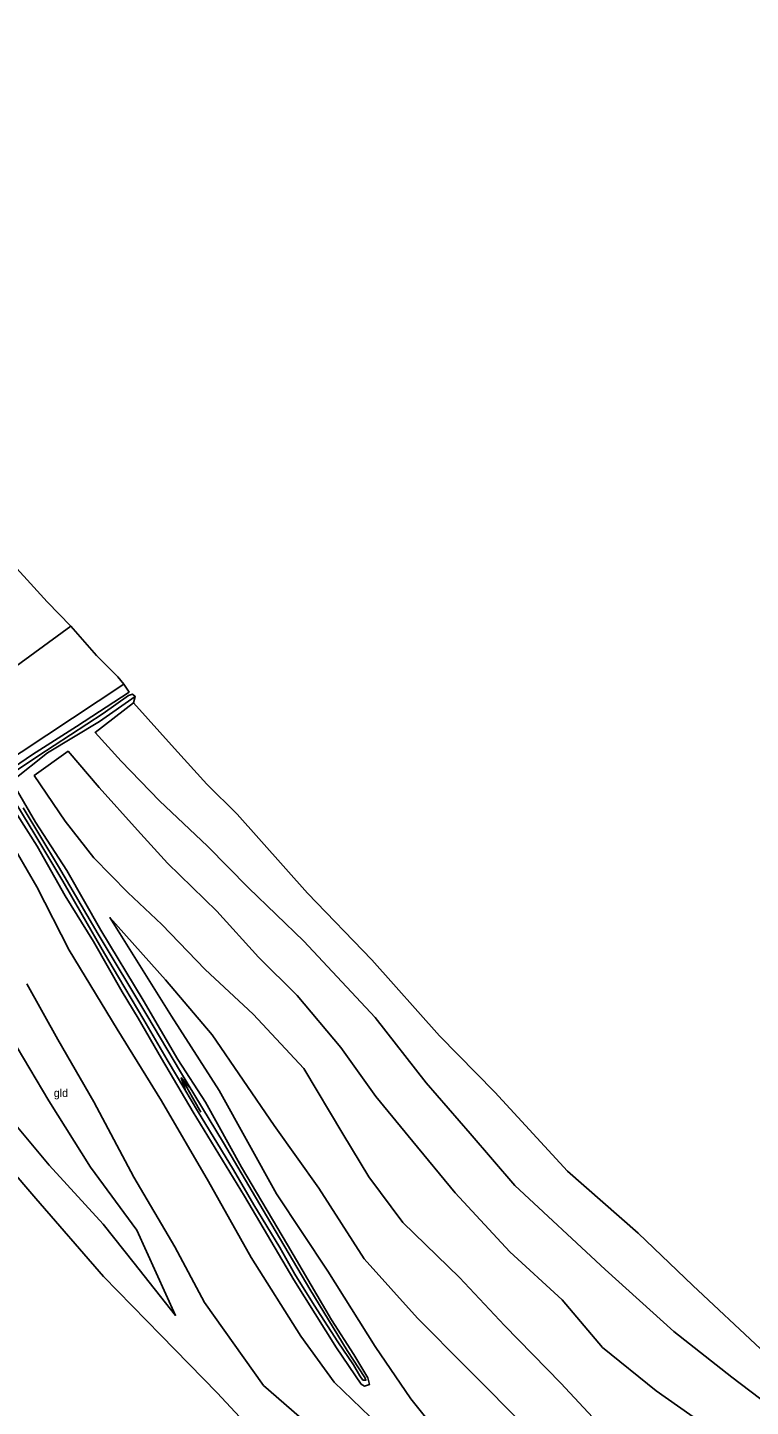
# Model space of a CAD drawing. Extents: x 154825 to 158680, y 370717 to 378075.
# Drawn here: x 155334.4 to 155424.8, y 377327.8 to 377500.1 of the extents above; entities that cross this region are included whole.
import ezdxf

# ---------------------------------------------------------------- set-up
doc = ezdxf.new("R2010")
doc.units = 0
for name, color, linetype in [('cultuurscheiding', 7, 'Continuous'), ('grasland_productiegrasl(vs)', 7, 'Continuous'), ('hoogteverschillijn', 7, 'Continuous'), ('insteek sloot', 7, 'Continuous'), ('Sloot bodem', 7, 'Continuous'), ('stroomrichting  watergangen', 7, 'Continuous'), ('vlak_akkerland', 7, 'Continuous'), ('vlak_Bos', 7, 'Continuous'), ('vlak_Grasland', 7, 'Continuous'), ('vlak_Grazige_vegetatie', 7, 'Continuous')]:
    doc.layers.add(name, color=color, linetype=linetype)

msp = doc.modelspace()

# ---------------------------------------------------------------- linework, layer by layer
at = {"layer": 'cultuurscheiding'}
msp.add_lwpolyline([(155308.09, 377402.13), (155339.81, 377425.31)], dxfattribs=at)
at = {"layer": 'hoogteverschillijn'}
for points in [[(155345.69, 377418.94), (155343.05, 377421.61), (155339.81, 377425.31), (155336.86, 377428.35), (155331.01, 377434.77), (155328.82, 377437.22), (155325.13, 377441.16), (155319.36, 377447.52), (155315.71, 377451.41), (155307.43, 377460.53), (155304.18, 377464.14), (155296.66, 377472.4), (155289.32, 377480.42), (155286.49, 377483.54), (155277.99, 377492.89), (155272.59, 377498.64), (155264.04, 377508.09)], [(155431.86, 377324.38), (155422.53, 377331.44), (155415.24, 377337.17), (155406.68, 377344.9), (155395.37, 377355.4), (155389.8, 377361.89), (155384.27, 377368.22), (155377.9, 377376.37), (155368.99, 377385.91), (155362.04, 377392.58), (155356.93, 377397.79), (155350.92, 377403.47), (155346.14, 377408.41), (155342.86, 377411.99), (155347.67, 377415.7), (155352.79, 377409.99), (155356.85, 377405.55), (155360.64, 377401.81), (155369.42, 377391.91), (155377.47, 377383.61), (155385.94, 377374.1), (155392.86, 377367.05), (155401.97, 377357.18), (155410.79, 377349.42), (155417.64, 377342.88), (155426.1, 377334.99)], [(155407.36, 377323.99), (155401.12, 377330.71), (155394.08, 377337.91), (155388.46, 377343.89), (155381.35, 377350.76), (155377.11, 377356.48), (155373.85, 377361.84), (155368.96, 377370.03), (155362.64, 377376.82), (155356.65, 377382.39), (155351.23, 377388.02), (155346.98, 377392.01), (155342.7, 377396.35), (155339.13, 377400.91), (155335.26, 377406.61), (155339.49, 377409.65), (155343.37, 377405.14), (155348.17, 377399.81), (155351.91, 377395.68), (155358.08, 377389.66), (155363.29, 377383.92), (155368.15, 377379.12), (155373.62, 377372.65), (155377.97, 377366.51), (155382.59, 377360.9), (155387.92, 377354.49), (155394.75, 377347.11), (155401.3, 377341.11), (155406.33, 377335.16), (155413.03, 377329.72), (155421.48, 377323.81)], [(155330.7, 377401.06), (155335.57, 377392.72), (155339.63, 377384.81), (155345.62, 377374.95), (155351.17, 377365.97), (155357.03, 377355.9), (155362.38, 377346.4), (155368.59, 377336.57), (155372.76, 377330.83), (155377.26, 377326.47)], [(155390.44, 377318.66), (155382.35, 377328.72), (155377.89, 377335.29), (155371.96, 377344.67), (155365.55, 377354.35), (155358.39, 377367.26), (155352.41, 377376.57), (155344.71, 377388.88), (155351.68, 377381.1), (155357.52, 377374.21), (155365.25, 377362.89), (155370.85, 377355.06), (155376.51, 377346.25), (155383.2, 377338.81), (155389.23, 377332.72), (155397.25, 377324.7)], [(155371.27, 377324.01), (155363.93, 377330.42), (155356.54, 377340.78), (155352.84, 377347.74), (155347.73, 377356.45), (155342.72, 377365.85), (155338.21, 377373.66), (155334.34, 377380.6)], [(155332.32, 377373.98), (155337.09, 377365.98), (155342.27, 377357.68), (155348.08, 377349.81), (155352.94, 377339.16), (155347.75, 377345.67), (155343.86, 377350.56), (155337.12, 377357.92), (155331.91, 377364.19)], [(155328.22, 377362.13), (155335.45, 377353.76), (155343.9, 377344.01), (155351.07, 377336.69), (155358.13, 377329.5), (155366.03, 377321.03)]]:
    msp.add_lwpolyline(points, dxfattribs=at)
at = {"layer": 'insteek sloot'}
for points in [[(155211.48, 377507.88), (155226.17, 377491.27), (155237.93, 377478.16), (155255.88, 377458.77), (155264.39, 377449.32), (155266.19, 377447.17), (155270.04, 377443.34), (155275.44, 377437.23), (155279.4, 377432.67), (155280.56, 377431.47), (155285.74, 377425.85), (155291.46, 377420.27), (155297.9, 377412.84), (155308.09, 377402.13), (155313.54, 377396.56), (155319.32, 377400.17), (155333.61, 377409.55), (155346.46, 377418.03)], [(155332.6, 377406.06), (155336.93, 377409.48), (155343.4, 377413.36), (155347.88, 377416.5)], [(155331.8, 377403.82), (155335.61, 377397.78), (155339.14, 377391.61), (155342.65, 377385.87), (155346.26, 377379.6), (155348.25, 377376.29), (155351.17, 377371.27), (155355.14, 377364.54), (155361.56, 377354.07), (155367.74, 377343.6), (155373.07, 377335.12), (155376.13, 377330.59), (155376.56, 377330.32), (155377.17, 377330.51), (155376.97, 377331.36), (155375.24, 377334.28), (155372.44, 377338.61), (155366.94, 377347.98), (155361.17, 377357.68), (155356.66, 377365.8), (155353.22, 377371.12), (155348.86, 377378.57), (155343.58, 377387.32), (155339.34, 377394.76), (155335.42, 377400.78), (155333.17, 377404.67)]]:
    msp.add_lwpolyline(points, dxfattribs=at)
at = {"layer": 'Sloot bodem'}
for points in [[(155347.12, 377417.06), (155340.53, 377412.76), (155335.04, 377409.24), (155330.12, 377405.94), (155324.11, 377401.87), (155318.77, 377398.4), (155313.44, 377395.03), (155312.14, 377395.39), (155307.02, 377401.4), (155301.34, 377408.02), (155295.09, 377414.71), (155288.68, 377421.64), (155284.49, 377426.14), (155280.98, 377430.05), (155279.64, 377431.57), (155162.2, 377561.27), (155165.81, 377563.59), (155174.08, 377568.62), (155176.77, 377570.24), (155185.45, 377575.46), (155195.56, 377581.85)], [(155332.14, 377406.66), (155335.71, 377409.06), (155339.79, 377411.73), (155343.88, 377414.38), (155347.04, 377416.61), (155347.54, 377416.79)], [(155332.23, 377404.34), (155335.33, 377399.24), (155338.82, 377393.43), (155341.23, 377389.22), (155344.06, 377384.4), (155345.79, 377381.43), (155348.96, 377376.1), (155351.89, 377371.09), (155354.1, 377367.41), (155355.68, 377364.74), (155360.19, 377357.36), (155362.72, 377352.99), (155365.98, 377347.65), (155367.83, 377344.3), (155370.25, 377340.46), (155373.21, 377335.86), (155375.19, 377332.97), (155375.98, 377331.61), (155376.36, 377331.09), (155376.74, 377331.05), (155376.62, 377331.41), (155374.41, 377334.79), (155369.74, 377342.43), (155363.89, 377352.32), (155358.94, 377360.72), (155353.56, 377369.58), (155349.32, 377376.66), (155343.25, 377386.79), (155338.29, 377395.25), (155333.85, 377402.59)]]:
    msp.add_lwpolyline(points, dxfattribs=at)
at = {"layer": 'stroomrichting  watergangen'}
for p, q in [((155353.62, 377368.87), (155354.15, 377367.38)), ((155356.1, 377364.55), (155353.63, 377368.89)), ((155353.63, 377368.89), (155354.64, 377367.67))]:
    msp.add_line(p, q, dxfattribs=at)
at = {"layer": 'vlak_akkerland'}
for points in [[(155332.6, 377406.06), (155336.93, 377409.48), (155343.4, 377413.36), (155347.88, 377416.5), (155347.67, 377415.7), (155352.79, 377409.99), (155356.85, 377405.55), (155360.64, 377401.81), (155369.42, 377391.91), (155377.47, 377383.61), (155385.94, 377374.1), (155392.86, 377367.05), (155401.97, 377357.18), (155410.79, 377349.42), (155417.64, 377342.88), (155426.1, 377334.99), (155439.54, 377329.02), (155446.29, 377327.48), (155453.96, 377349.87), (155459.15, 377324.59)], [(155331.8, 377403.82), (155335.61, 377397.78), (155339.14, 377391.61), (155342.65, 377385.87), (155346.26, 377379.6), (155348.25, 377376.29), (155351.17, 377371.27), (155355.14, 377364.54), (155361.56, 377354.07), (155367.74, 377343.6), (155373.07, 377335.12), (155376.13, 377330.59), (155376.56, 377330.32), (155377.17, 377330.51), (155376.97, 377331.36), (155375.24, 377334.28), (155372.44, 377338.61), (155366.94, 377347.98), (155361.17, 377357.68), (155356.66, 377365.8), (155353.22, 377371.12), (155348.86, 377378.57), (155343.58, 377387.32), (155339.34, 377394.76), (155335.42, 377400.78), (155333.17, 377404.67)], [(155366.03, 377321.03), (155358.13, 377329.5), (155351.07, 377336.69), (155343.9, 377344.01), (155335.45, 377353.76), (155328.22, 377362.13)]]:
    msp.add_lwpolyline(points, dxfattribs=at)
at = {"layer": 'vlak_Bos'}
msp.add_lwpolyline([(155319.32, 377400.17), (155313.54, 377396.56), (155308.09, 377402.13), (155339.81, 377425.31), (155343.05, 377421.61), (155345.69, 377418.94), (155346.46, 377418.03), (155333.61, 377409.55)], close=True, dxfattribs=at)
at = {"layer": 'vlak_Grasland'}
msp.add_lwpolyline([(155331.01, 377434.77), (155336.86, 377428.35), (155339.81, 377425.31), (155308.09, 377402.13)], dxfattribs=at)
at = {"layer": 'vlak_Grazige_vegetatie'}
for points in [[(155333.61, 377409.55), (155346.46, 377418.03), (155347.12, 377417.06), (155340.53, 377412.76), (155335.04, 377409.24), (155330.12, 377405.94)], [(155332.14, 377406.66), (155335.71, 377409.06), (155339.79, 377411.73), (155343.88, 377414.38), (155347.04, 377416.61), (155347.54, 377416.79), (155347.88, 377416.5), (155343.4, 377413.36), (155336.93, 377409.48), (155332.6, 377406.06)], [(155333.17, 377404.67), (155335.42, 377400.78), (155339.34, 377394.76), (155343.58, 377387.32), (155348.86, 377378.57), (155353.22, 377371.12), (155356.66, 377365.8), (155361.17, 377357.68), (155366.94, 377347.98), (155372.44, 377338.61), (155375.24, 377334.28), (155376.97, 377331.36), (155377.17, 377330.51), (155376.56, 377330.32), (155376.13, 377330.59), (155373.07, 377335.12), (155367.74, 377343.6), (155361.56, 377354.07), (155355.14, 377364.54), (155351.17, 377371.27), (155348.25, 377376.29), (155346.26, 377379.6), (155342.65, 377385.87), (155339.14, 377391.61), (155335.61, 377397.78), (155331.8, 377403.82)], [(155332.23, 377404.34), (155335.33, 377399.24), (155338.82, 377393.43), (155341.23, 377389.22), (155344.06, 377384.4), (155345.79, 377381.43), (155348.96, 377376.1), (155351.89, 377371.09), (155354.1, 377367.41), (155355.68, 377364.74), (155360.19, 377357.36), (155362.72, 377352.99), (155365.98, 377347.65), (155367.83, 377344.3), (155370.25, 377340.46), (155373.21, 377335.86), (155375.19, 377332.97), (155375.98, 377331.61), (155376.36, 377331.09), (155376.74, 377331.05), (155376.62, 377331.41), (155374.41, 377334.79), (155369.74, 377342.43), (155363.89, 377352.32), (155358.94, 377360.72), (155353.56, 377369.58), (155349.32, 377376.66), (155343.25, 377386.79), (155338.29, 377395.25), (155333.85, 377402.59)]]:
    msp.add_lwpolyline(points, dxfattribs=at)

# ---------------------------------------------------------------- texts
at = {"layer": 'grasland_productiegrasl(vs)'}
msp.add_text('gld', height=1, dxfattribs=at).set_placement((155337.7, 377366.46))

doc.saveas('drawing.dxf')
